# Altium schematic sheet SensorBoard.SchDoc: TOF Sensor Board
size A4; Author: Iman Ostovar; CompanyName: ETH Zürich; DrawnBy: Iman Ostovar; Engineer: Iman Ostovar; Organization: PBL; DocumentNumber: Master Project; Revision: A; SheetNumber: 1; SheetTotal: 1; Project: Sensor Shield for Drone
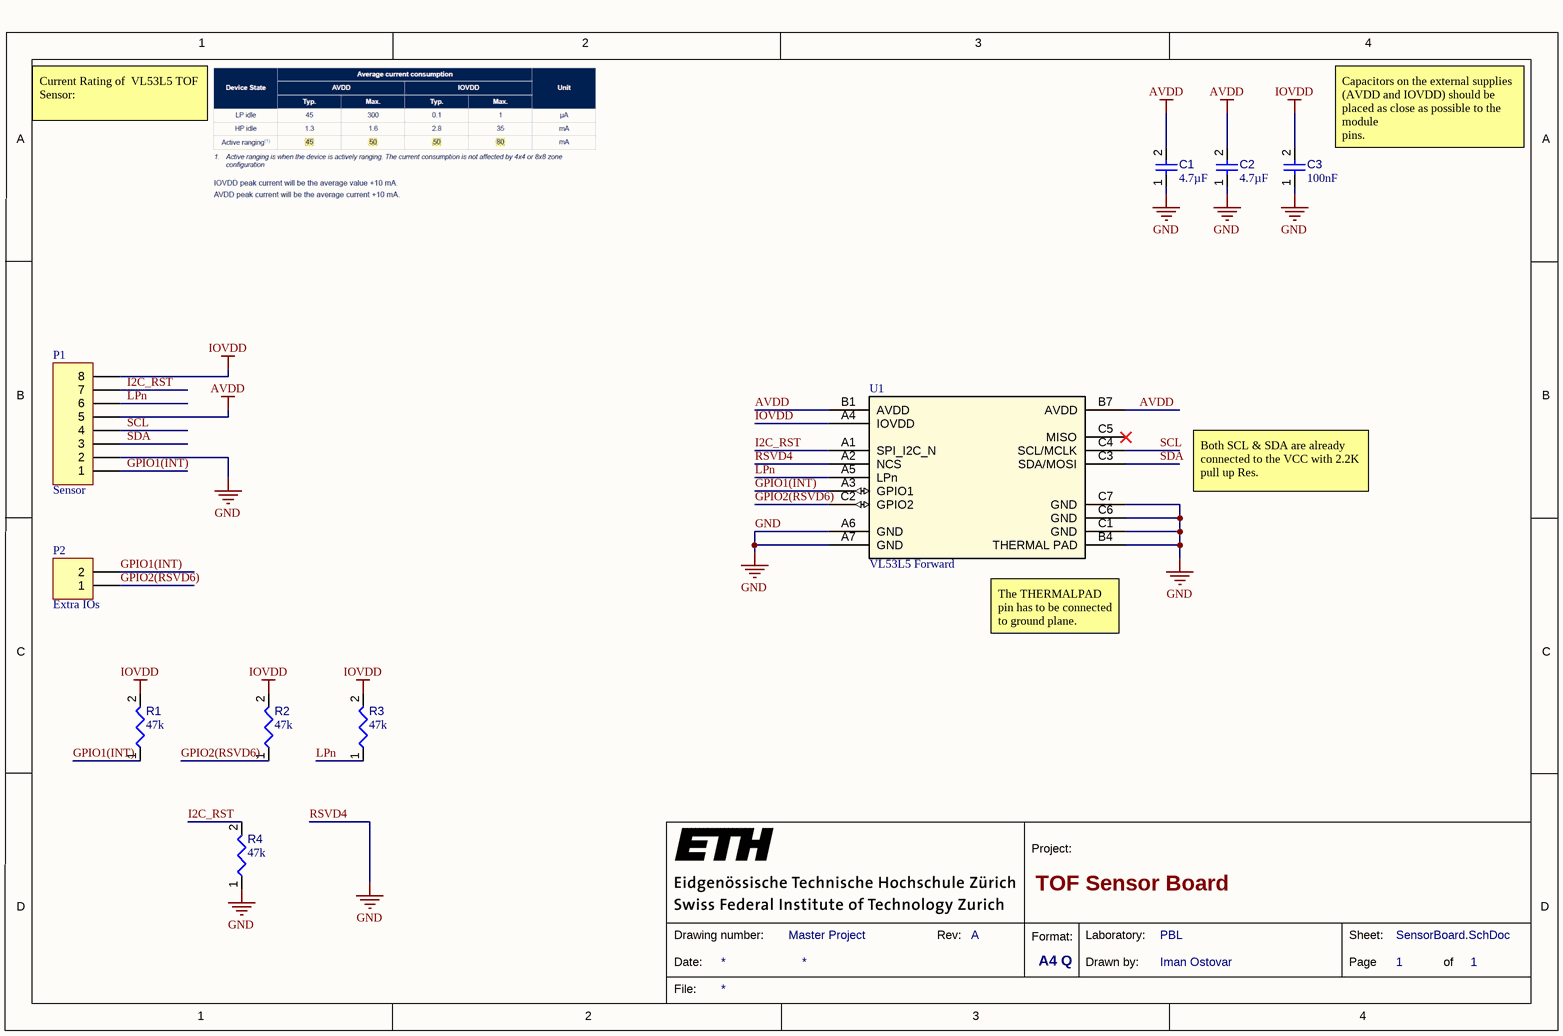
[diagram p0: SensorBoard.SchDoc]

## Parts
C1  value 4.7µF  [CAPC1005X55X25ML5T10]  (hidden comment: Capacitor 1 uF +/- 10% 6.3 V 1005)
C2  value 4.7µF  [CAPC1005X55X25ML5T10]  (hidden comment: Capacitor 1 uF +/- 10% 6.3 V 1005)
C3  value 100nF  [CAPC0402(1005)60_L]  (hidden comment: Capacitor 100nF +/-20% 25V 0402)
P1  Sensor  [MHDR1X8]
P2  Extra IOs  [MHDR1X2]
R1  value 47k  [RESC0402(1005)_L]  (hidden comment: Resistor 47K5 +/-1 % 0402 63 mW)
R2  value 47k  [RESC0402(1005)_L]  (hidden comment: Resistor 47K5 +/-1 % 0402 63 mW)
R3  value 47k  [RESC0402(1005)_L]  (hidden comment: Resistor 47K5 +/-1 % 0402 63 mW)
R4  value 47k  [RESC0402(1005)_L]  (hidden comment: Resistor 47K5 +/-1 % 0402 63 mW)
U1  VL53L5 Forward  [ARRAY_53L5_STM]

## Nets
AVDD: C1.2 C2.2 P1.5 U1.B1(AVDD) U1.B7(AVDD)
GND: C1.1 C2.1 C3.1 P1.2 R4.1 U1.A2(NCS) U1.A6(GND) U1.A7(GND) U1.B4(THERMAL_PAD) U1.C1(GND) U1.C6(GND) U1.C7(GND)  [also labelled RSVD4]
IOVDD: C3.2 P1.8 R1.2 R2.2 R3.2 U1.A4(IOVDD)
GPIO1(INT): P1.1 P2.2 R1.1 U1.A3(GPIO1)
GPIO2(RSVD6): P2.1 R2.1 U1.C2(GPIO2)
I2C_RST: P1.7 R4.2 U1.A1(SPI_I2C_N)
LPn: P1.6 R3.1 U1.A5(LPn)
SCL: P1.4 U1.C4(SCL/MCLK)
SDA: P1.3 U1.C3(SDA/MOSI)

Not connected (* = marked no-connect by the designer): U1 C5(MISO)*

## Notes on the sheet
- Current Rating of  VL53L5 TOF Sensor:
- (near C3) Capacitors on the external supplies (AVDD and IOVDD) should be placed as close as possible to the module
  pins.
- Both SCL & SDA are already connected to the VCC with 2.2K pull up Res.
- (near U1) The THERMALPAD pin has to be connected to ground plane.

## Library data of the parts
C1 C2 = CMP-001-00009-6: Chip Capacitor, 1 uF, +/- 10%, 6.3 V, 1005 (0402 Metric); Voltage Rating: 6.3V; Capacitor Type: Ceramic
C3 = CMP-001-00065-4: Chip Capacitor, 100nF +/-20%, 25V, 0402, Thickness 0.6 mm; Tolerance: 10%
P1 = MHDR1X8: Header, 8-Pin; System: Connector
P2 = MHDR1X2: Header, 2-Pin
R1-R4 = CMP-009-00137-3: Chip Resistor, 47,5 kOhms, +/-1 %, 63 mW, -55 to 155 degC, 0402; Power: 63mW; Tolerance: 1%
U1 = VL53L5: No Description Available; Built_By: EMA_Matt; Vendor: STMicroelectronics; SourceLibrary: Update_to_database_2021-02-23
